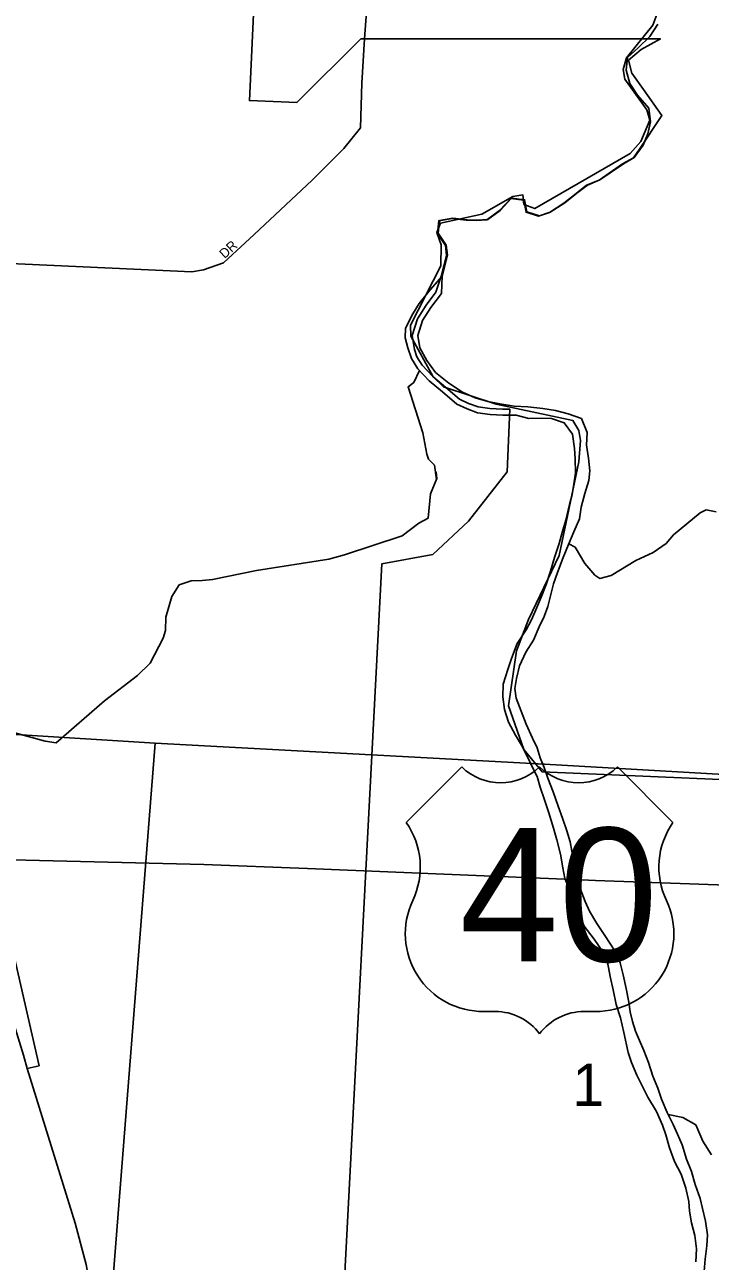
# Model space of a CAD drawing. Extents: x 0 to 40.4, y 0 to 22.
# Drawn here: x 7.209 to 7.886, y 16.73 to 17.952 of the extents above; entities that cross this region are included whole.
import ezdxf

# ---------------------------------------------------------------- set-up
doc = ezdxf.new("R2010")
doc.units = 0
for name, color, linetype in [('GM_X_City_Street', 7, 'Continuous'), ('GM_X_City_Street_Text', 7, 'Continuous'), ('GM_X_Corporation', 7, 'Continuous'), ('GM_X_Interchange_Ramps', 7, 'Continuous'), ('GM_X_Major_River', 7, 'Continuous'), ('GM_X_Minor_River', 7, 'Continuous'), ('GM_X_Section', 7, 'Continuous'), ('GM_X_Section_Text', 7, 'Continuous'), ('GM_X_State_Route', 7, 'Continuous'), ('GM_X_Township', 7, 'Continuous'), ('GM_X_Township_Subdivision', 7, 'Continuous'), ('GM_X_US_Route', 7, 'Continuous'), ('GM_X_US_Shield', 7, 'Continuous')]:
    doc.layers.add(name, color=color, linetype=linetype)

msp = doc.modelspace()

# ---------------------------------------------------------------- linework, layer by layer
at = {"layer": 'GM_X_City_Street'}
msp.add_lwpolyline([(7.1092, 17.7203), (7.1519, 17.7177), (7.3742, 17.7074), (7.3858, 17.7093), (7.4054, 17.7165), (7.4358, 17.7443), (7.4931, 17.7982), (7.5243, 17.8294), (7.5409, 17.8499), (7.5422, 17.894), (7.5446, 17.9376)], dxfattribs=at)
at = {"layer": 'GM_X_Corporation'}
msp.add_lwpolyline([(7.435, 17.962), (7.431, 17.8767), (7.4778, 17.8749), (7.5413, 17.9376), (7.8372, 17.9376), (7.8181, 17.9273), (7.8056, 17.9166), (7.809, 17.9038), (7.8204, 17.8878), (7.8386, 17.8621), (7.8166, 17.8286), (7.8105, 17.8201), (7.7999, 17.8141), (7.7866, 17.805), (7.7767, 17.7982), (7.7642, 17.793), (7.754, 17.785), (7.7419, 17.7752), (7.7275, 17.7662), (7.7168, 17.7624), (7.7044, 17.7663), (7.7022, 17.7784), (7.6893, 17.78), (7.6783, 17.7679), (7.6658, 17.7589), (7.6552, 17.7581), (7.6454, 17.7586), (7.6314, 17.7601), (7.6181, 17.7579), (7.6169, 17.7454), (7.6248, 17.7336), (7.6259, 17.7237), (7.6206, 17.7031), (7.6154, 17.6875), (7.6056, 17.6746), (7.5971, 17.661), (7.592, 17.6446), (7.5941, 17.6306), (7.5965, 17.6235), (7.6017, 17.6151), (7.6123, 17.604), (7.6253, 17.5932), (7.6386, 17.5815), (7.6477, 17.5774), (7.6571, 17.5739), (7.6686, 17.5725), (7.6811, 17.5717), (7.6884, 17.5717), (7.6859, 17.5099), (7.6477, 17.4609), (7.6123, 17.4281), (7.5619, 17.419), (7.5207, 16.6294)], dxfattribs=at)
at = {"layer": 'GM_X_Interchange_Ramps'}
msp.add_lwpolyline([(7.2113, 16.9201), (7.2232, 16.9228), (7.1912, 17.0626), (7.189, 17.0912), (7.189, 17.1031), (7.1893, 17.111), (7.1893, 17.1184), (7.1896, 17.1267)], dxfattribs=at)
at = {"layer": 'GM_X_Major_River'}
for points in [[(7.6214, 17.7033), (7.6267, 17.724), (7.6256, 17.7339), (7.6177, 17.7457), (7.6189, 17.7582), (7.6321, 17.7604), (7.6461, 17.7588), (7.6559, 17.7584), (7.6665, 17.7591), (7.679, 17.7682), (7.6901, 17.7803), (7.7029, 17.7787), (7.7051, 17.7666), (7.7176, 17.7627), (7.7282, 17.7665), (7.7426, 17.7755), (7.7547, 17.7853), (7.765, 17.7932), (7.7775, 17.7985), (7.7874, 17.8053), (7.8006, 17.8143), (7.8112, 17.8204), (7.82, 17.8325), (7.8249, 17.8438), (7.8273, 17.8556), (7.8258, 17.8692), (7.8145, 17.8821), (7.807, 17.8936), (7.8033, 17.9068), (7.8048, 17.9193), (7.8151, 17.9288), (7.8269, 17.9401), (7.8345, 17.9522)], [(7.6214, 17.7033), (7.6095, 17.6896), (7.5989, 17.676), (7.5924, 17.6658), (7.5852, 17.6518)], [(7.6149, 17.6081), (7.6062, 17.6198), (7.5995, 17.6324), (7.5976, 17.6445), (7.6022, 17.6593), (7.6102, 17.6721), (7.6209, 17.6861), (7.6214, 17.7033)], [(7.5852, 17.6518), (7.5851, 17.6423), (7.5877, 17.6324), (7.5911, 17.6218), (7.5975, 17.6115), (7.6088, 17.5997), (7.622, 17.5887), (7.6359, 17.5765), (7.6461, 17.5719), (7.6563, 17.5681), (7.6688, 17.5665), (7.6816, 17.5657), (7.6945, 17.5657), (7.7073, 17.5626), (7.7194, 17.5629), (7.7296, 17.5625), (7.7421, 17.5583), (7.7504, 17.5469), (7.7522, 17.5328), (7.7529, 17.5226), (7.7532, 17.5089), (7.7517, 17.4976), (7.7501, 17.4873), (7.7474, 17.4775), (7.7436, 17.462), (7.7401, 17.4498), (7.7371, 17.4389), (7.7325, 17.4252), (7.7286, 17.4116), (7.7244, 17.3983), (7.7194, 17.3859), (7.7152, 17.3756), (7.7099, 17.3635), (7.7046, 17.3537), (7.6958, 17.3401), (7.6901, 17.3253), (7.6863, 17.3143), (7.6817, 17.2999), (7.6816, 17.2874), (7.6831, 17.2749), (7.6872, 17.2624), (7.6939, 17.2495), (7.6999, 17.2396), (7.7059, 17.2282), (7.7104, 17.2183), (7.7153, 17.2088), (7.7183, 17.1982), (7.7228, 17.1857), (7.7269, 17.1727), (7.7317, 17.1576), (7.7347, 17.1462), (7.7384, 17.1318), (7.7407, 17.1185), (7.7429, 17.1078), (7.7481, 17.0957), (7.7537, 17.0832), (7.7564, 17.0737), (7.762, 17.0608), (7.7718, 17.0478), (7.7808, 17.0345), (7.7849, 17.025), (7.7875, 17.011), (7.7905, 16.9977), (7.7934, 16.9833), (7.7979, 16.97), (7.8009, 16.9556), (7.8053, 16.9359), (7.8087, 16.926), (7.8139, 16.9134), (7.8196, 16.9024), (7.8248, 16.8918), (7.8334, 16.8774), (7.8394, 16.8641), (7.8424, 16.8546), (7.8462, 16.8417), (7.851, 16.828), (7.8578, 16.8155), (7.8623, 16.8018), (7.8652, 16.7885), (7.8659, 16.779), (7.8678, 16.7676), (7.8711, 16.7551), (7.873, 16.7418), (7.8722, 16.729)], [(7.8804, 16.7198), (7.8816, 16.7316), (7.8832, 16.7448), (7.8836, 16.7558), (7.8818, 16.7691), (7.8788, 16.7816), (7.8766, 16.7915), (7.8717, 16.8055), (7.868, 16.8181), (7.8631, 16.8306), (7.8586, 16.8446), (7.8542, 16.8553), (7.8497, 16.8648), (7.844, 16.8766), (7.8384, 16.8898), (7.8347, 16.9005), (7.8298, 16.9126), (7.8253, 16.9259), (7.8208, 16.9377), (7.8167, 16.9476), (7.8126, 16.9571), (7.8096, 16.9665), (7.8074, 16.976), (7.8059, 16.9855), (7.8033, 16.9992), (7.8003, 17.0125), (7.7974, 17.0246), (7.7914, 17.0375), (7.7831, 17.0504), (7.7745, 17.0634), (7.767, 17.0755), (7.7628, 17.085), (7.758, 17.0979), (7.7546, 17.1082), (7.752, 17.1211), (7.7498, 17.1347), (7.7479, 17.1442), (7.7446, 17.1549), (7.7405, 17.1674), (7.736, 17.1792), (7.7311, 17.1936), (7.7259, 17.2069), (7.7222, 17.2175), (7.7184, 17.227), (7.7154, 17.2369), (7.7109, 17.2467), (7.7046, 17.2604), (7.6997, 17.2733), (7.6945, 17.2862), (7.6934, 17.2957), (7.6949, 17.3056), (7.698, 17.3181), (7.7041, 17.3317), (7.7117, 17.3434), (7.7174, 17.3567), (7.7224, 17.3669), (7.7258, 17.3767), (7.7289, 17.3885), (7.7316, 17.3991), (7.7354, 17.4104), (7.7412, 17.4252), (7.7465, 17.4381), (7.7515, 17.4506), (7.7572, 17.4634), (7.7588, 17.4748), (7.7626, 17.4884), (7.7664, 17.5013), (7.7676, 17.5108), (7.7661, 17.5233), (7.7643, 17.5362), (7.7647, 17.5487), (7.7591, 17.5624), (7.7459, 17.567), (7.7334, 17.5704), (7.721, 17.5724), (7.7062, 17.574), (7.6926, 17.5748), (7.6786, 17.5771), (7.6665, 17.5794), (7.6541, 17.5829), (7.6416, 17.5886), (7.6281, 17.5974), (7.6149, 17.6081)]]:
    msp.add_lwpolyline(points, dxfattribs=at)
at = {"layer": 'GM_X_Minor_River'}
for points in [[(7.599, 17.61), (7.5935, 17.5981), (7.5879, 17.5939), (7.6025, 17.5484), (7.6062, 17.5272), (7.6081, 17.5223), (7.6138, 17.5162), (7.6159, 17.5021)], [(7.1993, 17.2519), (7.2291, 17.2435), (7.2401, 17.242), (7.2878, 17.2836), (7.3204, 17.3086), (7.3329, 17.3207), (7.3458, 17.3453), (7.348, 17.3529), (7.3484, 17.3662), (7.3542, 17.3866), (7.3617, 17.398), (7.3735, 17.4021), (7.3844, 17.4025), (7.3946, 17.4032), (7.4381, 17.4122), (7.5096, 17.4235), (7.5251, 17.4276), (7.5819, 17.4465), (7.5986, 17.459), (7.6076, 17.4639), (7.61, 17.4881), (7.6164, 17.5033), (7.6157, 17.5097)], [(7.7467, 17.4386), (7.7531, 17.4352), (7.7626, 17.4192), (7.7724, 17.4078), (7.7773, 17.4044), (7.7886, 17.4074), (7.8129, 17.4221), (7.8299, 17.4301), (7.8428, 17.4388), (7.85, 17.4475), (7.8765, 17.4694), (7.8825, 17.4721), (7.8924, 17.4701)], [(7.845, 16.8746), (7.8594, 16.8715), (7.8722, 16.8643), (7.879, 16.8484), (7.8877, 16.8347)]]:
    msp.add_lwpolyline(points, dxfattribs=at)
at = {"layer": 'GM_X_Section'}
for points in [[(6.4444, 17.2982), (6.915, 17.2679), (7.3378, 17.2417), (7.2909, 16.6427), (7.1996, 16.6471), (6.6625, 16.6858), (6.3929, 16.7053), (6.4106, 16.9046)], [(7.3378, 17.2417), (7.7228, 17.2207), (8.2373, 17.1912), (8.202, 16.6562), (8.1953, 16.5941), (7.7054, 16.6198), (7.2909, 16.6427)]]:
    msp.add_lwpolyline(points, close=True, dxfattribs=at)
at = {"layer": 'GM_X_State_Route'}
msp.add_lwpolyline([(7.2747, 16.6438), (7.2755, 16.6702), (7.2751, 16.6952), (7.2696, 16.7262), (7.2587, 16.7671), (7.2113, 16.9201), (7.2077, 16.9333), (7.1476, 17.1281)], dxfattribs=at)
at = {"layer": 'GM_X_Township'}
msp.add_lwpolyline([(8.1794, 17.1936), (7.7202, 17.2134), (7.7022, 17.2353), (7.6871, 17.2784), (7.695, 17.3329), (7.707, 17.3638), (7.7372, 17.427), (7.7567, 17.5196), (7.7582, 17.5409), (7.7566, 17.5507), (7.7507, 17.5605), (7.6749, 17.5765), (7.6227, 17.5939), (7.6127, 17.6036), (7.5904, 17.6439), (7.5902, 17.6546), (7.6201, 17.7135), (7.6205, 17.7341), (7.6162, 17.7462), (7.6198, 17.7557), (7.6607, 17.7643), (7.6912, 17.7819), (7.7014, 17.7835), (7.7023, 17.7741), (7.713, 17.77), (7.8074, 17.8243), (7.8179, 17.8362), (7.8267, 17.8573), (7.8238, 17.8675), (7.8021, 17.8979), (7.8005, 17.9074), (7.8037, 17.9188), (7.8298, 17.9511), (7.8338, 17.9618)], dxfattribs=at)
at = {"layer": 'GM_X_Township_Subdivision'}
msp.add_lwpolyline([(7.2117, 18.3707), (7.2503, 18.3682), (7.3843, 18.3604), (7.426, 18.3588), (7.4821, 18.356), (7.4942, 18.3555), (7.5008, 18.3537), (7.5063, 18.3516), (7.5126, 18.3453), (7.5331, 18.3155), (7.5501, 18.2924), (7.5587, 18.2786), (7.5639, 18.268), (7.5639, 18.2587), (7.5542, 18.099), (7.5476, 17.9778), (7.5446, 17.9376)], dxfattribs=at)
at = {"layer": 'GM_X_US_Route'}
for points in [[(7.1596, 17.1277), (7.1896, 17.1267), (7.2102, 17.1261)], [(7.2102, 17.1261), (7.3859, 17.1218), (7.4883, 17.1176)], [(7.4883, 17.1176), (7.7663, 17.1062)], [(7.7663, 17.1062), (7.773, 17.1059), (8.0237, 17.0971), (8.1738, 17.0912), (8.2341, 17.089), (8.5244, 17.0778), (8.8632, 17.0678), (8.9515, 17.0658), (9.4, 17.0454)]]:
    msp.add_lwpolyline(points, dxfattribs=at)
at = {"layer": 'GM_X_US_Shield'}
for p, q in [((7.6409, 17.2181), (7.586, 17.1632)), ((7.8496, 17.1632), (7.7947, 17.2181)), ((7.6629, 16.9764), (7.6739, 16.9764)), ((7.7617, 16.9764), (7.7727, 16.9764))]:
    msp.add_line(p, q, dxfattribs=at)
for centre, radius, start, end in [((7.6793, 17.2573), 0.0549, 225.573, 314.427), ((7.7563, 17.2573), 0.0549, 225.573, 314.427), ((7.523, 17.1191), 0.0769, 334.5471, 35.0009), ((7.9126, 17.1191), 0.0769, 144.9991, 205.4529), ((7.662, 17.0533), 0.0769, 154.8319, 270.6383), ((7.7736, 17.0533), 0.0769, 269.3617, 25.1681), ((7.6739, 16.9215), 0.0549, 36.8699, 90), ((7.7617, 16.9215), 0.0549, 90, 143.1301)]:
    msp.add_arc(centre, radius, start, end, dxfattribs=at)

# ---------------------------------------------------------------- texts
at = {"layer": 'GM_X_City_Street_Text'}
msp.add_text('DR', height=0.00947, rotation=42.8801, dxfattribs=at).set_placement((7.4066, 17.72))
at = {"layer": 'GM_X_Section_Text'}
msp.add_text('1', height=0.0419, rotation=0, dxfattribs=at).set_placement((7.7503, 16.883))
at = {"layer": 'GM_X_US_Shield'}
msp.add_text('40', height=0.13184, dxfattribs=at).set_placement((7.6386, 17.0259))

doc.saveas('drawing.dxf')
